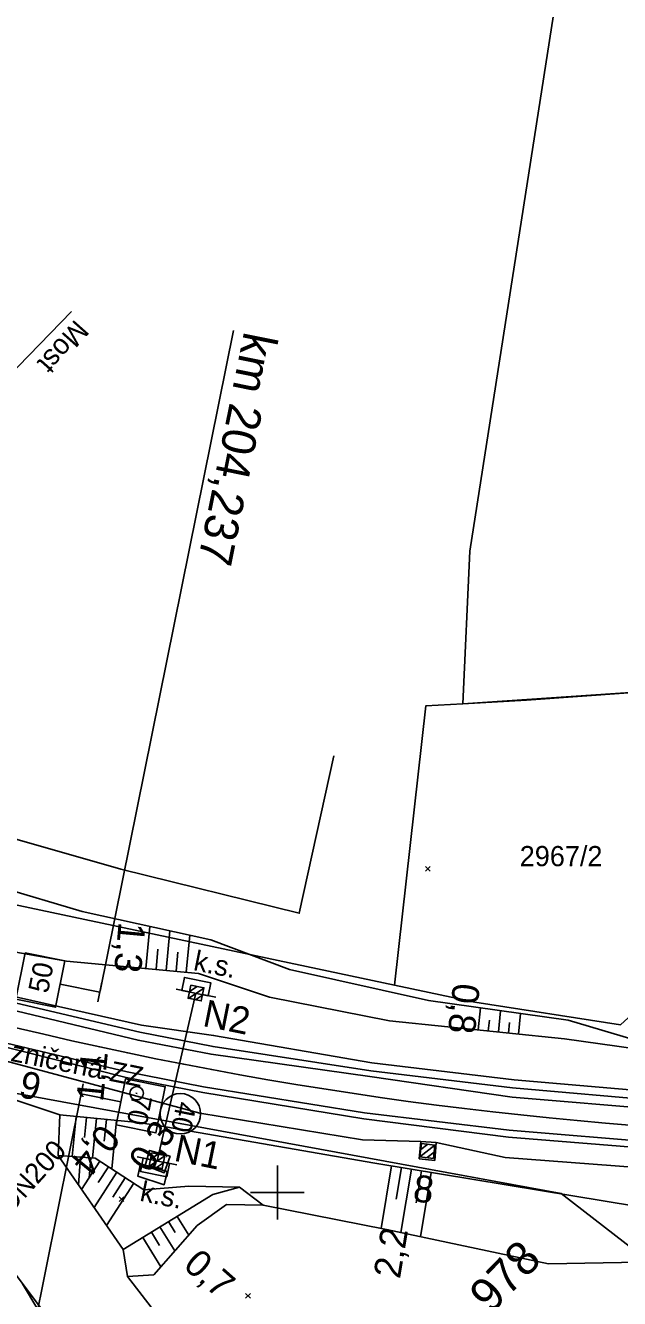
# Model space of a CAD drawing. Extents: x -800194 to -799078, y -1007177 to -1006597.
# Drawn here: x -799718.7 to -799674.6, y -1007007.9 to -1006913.4 of the extents above; entities that cross this region are included whole.
import ezdxf

# ---------------------------------------------------------------- set-up
doc = ezdxf.new("R2010")
doc.units = 0
for name, color, linetype in [('02_Osa_koleje', 7, 'Continuous'), ('Ramove udaje', 7, 'Continuous'), ('Vrstva 11', 7, 'Continuous'), ('Vrstva 12', 7, 'Continuous'), ('Vrstva 17', 7, 'Continuous'), ('Vrstva 18', 7, 'Continuous'), ('Vrstva 2', 7, 'Continuous'), ('Vrstva 23', 7, 'Continuous'), ('Vrstva 25', 7, 'Continuous'), ('Vrstva 4', 7, 'Continuous'), ('Vrstva 43', 7, 'Continuous'), ('Vrstva 48', 7, 'Continuous'), ('Vrstva 49', 7, 'Continuous'), ('Vrstva 5', 7, 'Continuous'), ('Vrstva 50', 7, 'Continuous'), ('Vrstva 53', 7, 'Continuous'), ('Vrstva 55', 7, 'Continuous'), ('Vrstva 57', 7, 'Continuous')]:
    doc.layers.add(name, color=color, linetype=linetype)

msp = doc.modelspace()

# ---------------------------------------------------------------- linework, layer by layer
at = {"layer": '02_Osa_koleje'}
msp.add_arc((-799651.022, -1006703.891), 292, 255.62486, 308.20516, dxfattribs=at)
at = {"layer": 'Ramove udaje'}
for p, q in [((-799700, -1006998), (-799700, -1007002)), ((-799702, -1007000), (-799700, -1007000)), ((-799700, -1007000), (-799698, -1007000))]:
    msp.add_line(p, q, dxfattribs=at)
at = {"layer": 'Vrstva 11'}
for p, q in [((-799706.526, -1006985.106), (-799707.506, -1006984.907)), ((-799706.602, -1006985.6), (-799705.452, -1006984.836)), ((-799706.525, -1006985.099), (-799705.943, -1006984.713)), ((-799706.036, -1006985.204), (-799708.923, -1006997.646)), ((-799706.082, -1006985.705), (-799705.557, -1006985.356)), ((-799705.546, -1006985.304), (-799704.566, -1006985.501)), ((-799689.419, -1006997.352), (-799688.31, -1006996.481)), ((-799689.355, -1006996.825), (-799688.836, -1006996.418)), ((-799709.413, -1006997.548), (-799710.393, -1006997.349)), ((-799709.489, -1006998.042), (-799708.339, -1006997.278)), ((-799709.412, -1006997.541), (-799708.83, -1006997.155)), ((-799688.896, -1006997.418), (-799688.37, -1006997.005)), ((-799708.969, -1006998.147), (-799708.444, -1006997.798)), ((-799708.433, -1006997.746), (-799707.453, -1006997.943))]:
    msp.add_line(p, q, dxfattribs=at)
for points in [[(-799706.427, -1006984.615), (-799705.447, -1006984.813), (-799705.645, -1006985.793), (-799706.625, -1006985.595)], [(-799689.3, -1006996.362), (-799688.307, -1006996.481), (-799688.426, -1006997.474), (-799689.419, -1006997.355)], [(-799709.314, -1006997.057), (-799708.334, -1006997.255), (-799708.532, -1006998.235), (-799709.512, -1006998.037)]]:
    msp.add_lwpolyline(points, close=True, dxfattribs=at)
at = {"layer": 'Vrstva 12'}
for p, q in [((-799709.809, -1006998.009), (-799709.806, -1006998.009)), ((-799708.388, -1006998.534), (-799708.385, -1006998.533))]:
    msp.add_line(p, q, dxfattribs=at)
for points in [[(-799689.347, -1006996.226), (-799688.222, -1006996.296), (-799688.323, -1006997.618), (-799689.475, -1006997.506), (-799689.347, -1006996.226)], [(-799707.958, -1006997.313), (-799708.385, -1006998.533), (-799709.809, -1006998.009), (-799709.473, -1006996.883)], [(-799707.958, -1006997.313), (-799709.473, -1006996.883), (-799709.806, -1006998.009), (-799708.388, -1006998.534), (-799707.958, -1006997.313)]]:
    msp.add_lwpolyline(points, dxfattribs=at)
at = {"layer": 'Vrstva 17'}
for points in [[(-799695.807, -1006967.611), (-799698.37, -1006979.283), (-799711.621, -1006976.014), (-799725.913, -1006971.918), (-799726.806, -1006975.491)], [(-799708.261, -1006998.95), (-799708.384, -1006999.431), (-799710.346, -1006998.801), (-799710.257, -1006998.331)]]:
    msp.add_lwpolyline(points, dxfattribs=at)
at = {"layer": 'Vrstva 18'}
msp.add_line((-799754.68, -1006975.182), (-799715.262, -1006934.616), dxfattribs=at)
at = {"layer": 'Vrstva 23'}
msp.add_lwpolyline([(-799710.163, -1006997.878), (-799708.18, -1006998.442), (-799708.384, -1006999.431), (-799710.346, -1006998.801), (-799710.163, -1006997.878)], dxfattribs=at)
at = {"layer": 'Vrstva 25'}
for points in [[(-799707.094, -1006985.017), (-799706.896, -1006984.037), (-799704.936, -1006984.433), (-799705.134, -1006985.413), (-799707.094, -1006985.017)], [(-799708.002, -1006997.857), (-799708.2, -1006998.837), (-799710.16, -1006998.441), (-799709.962, -1006997.461), (-799708.002, -1006997.857)]]:
    msp.add_lwpolyline(points, dxfattribs=at)
at = {"layer": 'Vrstva 4'}
for points in [[(-799766.319, -1006970.565), (-799760.949, -1006972.542), (-799747.638, -1006977.46), (-799730.549, -1006982.982), (-799710.066, -1006987.578), (-799704.728, -1006988.346), (-799693.001, -1006990.373), (-799682.434, -1006991.64), (-799671.27, -1006992.619), (-799659.31, -1006993.026), (-799648.69, -1006993.125), (-799637.398, -1006992.704), (-799625.913, -1006992.175), (-799614.965, -1006990.831), (-799603.911, -1006989.312), (-799592.728, -1006987.172), (-799581.605, -1006984.547), (-799570.583, -1006981.598), (-799559.909, -1006978.216), (-799542.956, -1006972.25), (-799531.79, -1006967.658), (-799521.285, -1006962.191), (-799511.236, -1006957.129)], [(-799779.678, -1006964.304), (-799766.319, -1006970.565), (-799761.253, -1006973.176), (-799747.77, -1006978.421), (-799730.774, -1006983.8), (-799710.333, -1006988.709), (-799704.916, -1006989.741), (-799693.131, -1006991.407), (-799682.585, -1006992.929), (-799671.325, -1006993.879), (-799659.363, -1006994.45), (-799648.66, -1006994.501), (-799637.23, -1006994.127), (-799626.066, -1006993.335), (-799614.788, -1006992.17), (-799603.669, -1006990.506), (-799592.467, -1006988.452), (-799581.281, -1006985.916), (-799570.22, -1006982.998), (-799559.296, -1006979.606), (-799542.375, -1006973.485), (-799531.236, -1006968.774), (-799520.48, -1006963.762), (-799510.394, -1006958.536)], [(-799776.864, -1006969.085), (-799770.965, -1006971.646), (-799761.91, -1006975.649), (-799748.544, -1006980.777), (-799731.457, -1006986.215), (-799711.132, -1006991.054), (-799705.482, -1006992.16), (-799693.53, -1006994.084), (-799682.801, -1006995.384), (-799671.514, -1006996.319), (-799659.449, -1006996.851), (-799648.588, -1006996.949), (-799637.262, -1006996.573), (-799625.835, -1006995.773), (-799614.546, -1006994.586), (-799603.199, -1006992.945), (-799591.969, -1006990.857), (-799580.647, -1006988.335), (-799569.534, -1006985.311), (-799558.557, -1006981.947), (-799541.405, -1006975.739), (-799530.263, -1006971.071), (-799519.455, -1006966), (-799509.248, -1006960.724)], [(-799776.864, -1006969.085), (-799771.262, -1006971.982), (-799762.131, -1006976.093), (-799748.706, -1006981.286), (-799731.51, -1006986.353), (-799711.222, -1006991.459), (-799705.527, -1006992.587), (-799693.582, -1006994.543), (-799682.85, -1006995.904), (-799671.5, -1006996.805), (-799659.556, -1006997.356), (-799648.616, -1006997.341), (-799637.276, -1006997.071), (-799625.828, -1006996.297), (-799614.43, -1006995.109), (-799603.18, -1006993.475), (-799591.849, -1006991.264), (-799580.564, -1006988.698), (-799569.449, -1006985.746), (-799558.385, -1006982.386), (-799541.268, -1006976.227), (-799530.102, -1006971.505), (-799519.398, -1006966.36), (-799509.087, -1006961.127)], [(-799779.011, -1006963.023), (-799770.632, -1006967.944), (-799766.319, -1006970.565), (-799761.021, -1006972.82), (-799747.748, -1006977.966), (-799730.719, -1006983.271), (-799710.195, -1006988.108), (-799704.765, -1006989.181), (-799693.072, -1006990.965), (-799682.554, -1006992.238), (-799671.266, -1006993.222), (-799659.388, -1006993.765), (-799648.658, -1006993.824), (-799637.385, -1006993.531), (-799625.769, -1006992.728), (-799614.9, -1006991.542), (-799603.91, -1006989.963), (-799592.572, -1006987.892), (-799581.421, -1006985.419), (-799570.327, -1006982.332), (-799559.429, -1006979.066), (-799542.601, -1006973.013), (-799531.454, -1006968.25), (-799520.744, -1006963.214)], [(-799776.864, -1006969.085), (-799771.693, -1006972.522), (-799762.217, -1006976.394), (-799748.898, -1006981.647), (-799733.68, -1006986.66), (-799728.795, -1006987.945), (-799711.349, -1006992.599), (-799705.744, -1006994.116), (-799693.689, -1006996.09), (-799689.347, -1006996.226), (-799688.222, -1006996.296), (-799683.105, -1006997.407), (-799671.667, -1006998.275)]]:
    msp.add_lwpolyline(points, dxfattribs=at)
at = {"layer": 'Vrstva 48'}
for p, q in [((-799709.746, -1006983.382), (-799709.457, -1006980.257)), ((-799708.252, -1006983.521), (-799707.98, -1006980.58)), ((-799706.759, -1006983.659), (-799706.504, -1006980.903)), ((-799708.999, -1006983.452), (-799708.859, -1006981.935)), ((-799707.506, -1006983.59), (-799707.374, -1006982.166)), ((-799685.1, -1006987.935), (-799684.931, -1006986.304)), ((-799683.608, -1006988.09), (-799683.444, -1006986.513)), ((-799682.116, -1006988.245), (-799681.958, -1006986.722)), ((-799684.354, -1006988.013), (-799684.271, -1006987.211)), ((-799682.862, -1006988.168), (-799682.782, -1006987.393)), ((-799714.916, -1006994.364), (-799715.209, -1006997.336)), ((-799714.169, -1006994.437), (-799714.315, -1006995.913)), ((-799713.423, -1006994.511), (-799713.712, -1006997.443)), ((-799712.677, -1006994.585), (-799712.835, -1006996.19)), ((-799711.93, -1006994.658), (-799712.285, -1006998.256)), ((-799714.594, -1006997.38), (-799714.742, -1006999.446)), ((-799713.846, -1006997.433), (-799713.954, -1006998.934)), ((-799713.165, -1006997.685), (-799714.519, -1006999.77)), ((-799712.536, -1006998.093), (-799713.297, -1006999.266)), ((-799691.538, -1006998.023), (-799692.31, -1007002.68)), ((-799690.798, -1006998.146), (-799691.187, -1007000.488)), ((-799690.058, -1006998.269), (-799690.841, -1007002.985)), ((-799689.318, -1006998.392), (-799689.712, -1007000.766)), ((-799711.907, -1006998.502), (-799713.599, -1007001.107)), ((-799710.649, -1006999.319), (-799712.678, -1007002.443)), ((-799711.278, -1006998.911), (-799712.208, -1007000.343)), ((-799688.579, -1006998.514), (-799689.372, -1007003.296)), ((-799708.066, -1007002.169), (-799707.578, -1007002.963)), ((-799707.427, -1007001.776), (-799706.571, -1007003.169)), ((-799709.344, -1007002.954), (-799708.736, -1007003.943)), ((-799708.705, -1007002.561), (-799707.609, -1007004.344)), ((-799709.983, -1007003.347), (-799708.648, -1007005.518))]:
    msp.add_line(p, q, dxfattribs=at)
at = {"layer": 'Vrstva 49'}
for p, q in [((-799689.011, -1006975.814), (-799688.657, -1006976.168)), ((-799689.011, -1006976.168), (-799688.657, -1006975.814)), ((-799716.248, -1006997.261), (-799716.141, -1006994.243)), ((-799711.736, -1007000.327), (-799711.382, -1007000.681)), ((-799711.736, -1007000.681), (-799711.382, -1007000.327)), ((-799702.358, -1007007.501), (-799702.004, -1007007.855)), ((-799702.358, -1007007.855), (-799702.004, -1007007.501))]:
    msp.add_line(p, q, dxfattribs=at)
for points in [[(-799710.319, -1006994.817), (-799708.871, -1006995.032), (-799692.771, -1006997.819), (-799673.296, -1007001.049), (-799659.562, -1007000.479), (-799648.457, -1007000.689), (-799625.451, -1006999.097), (-799615.697, -1006997.513), (-799614.57, -1006997.347), (-799602.963, -1006995.575), (-799579.498, -1006991.091), (-799558.66, -1006984.762), (-799544.861, -1006980.115), (-799538.187, -1006977.215), (-799529.217, -1006973.339), (-799517.856, -1006968.167), (-799516.556, -1006966.997), (-799515.527, -1006966.511), (-799507.817, -1006962.779)], [(-799728.174, -1006980.607), (-799726.806, -1006975.491), (-799714.47, -1006979.159), (-799704.928, -1006981.248), (-799699.097, -1006983.466), (-799688.779, -1006985.763), (-799678.423, -1006987.219), (-799669.363, -1006989.921)], [(-799728.174, -1006980.607), (-799715.637, -1006982.837), (-799705.851, -1006983.743), (-799700.586, -1006985.508), (-799691.67, -1006987.253), (-799678.693, -1006988.601), (-799669.363, -1006989.921)], [(-799733.039, -1007005.939), (-799736.26, -1007003.86), (-799742.34, -1006997.896), (-799743.342, -1006994.901), (-799739.871, -1006991.182), (-799734.968, -1006991.052), (-799728.642, -1006990.92), (-799723.01, -1006991.966), (-799716.141, -1006994.243), (-799710.319, -1006994.817)], [(-799716.248, -1006997.261), (-799711.439, -1007004.242), (-799711.113, -1007006.25), (-799707.442, -1007011.019), (-799702.585, -1007019.595), (-799698.243, -1007027.001), (-799684.872, -1007037.347), (-799668.902, -1007051.666)], [(-799716.248, -1006997.261), (-799713.515, -1006997.457), (-799709.895, -1006999.809), (-799706.577, -1006999.538), (-799702.816, -1006999.606), (-799701.051, -1007000.939), (-799691.907, -1007002.76), (-799679.882, -1007005.3), (-799670.416, -1007005.115), (-799649.119, -1007006.099), (-799641.812, -1007006.94)], [(-799702.816, -1006999.606), (-799704.779, -1007000.148), (-799711.439, -1007004.242)], [(-799711.113, -1007006.25), (-799709.167, -1007006.105), (-799705.943, -1007002.46), (-799703.761, -1007000.905), (-799701.051, -1007000.939)], [(-799718.907, -1007006.786), (-799714.515, -1007014.16), (-799704.214, -1007027.237), (-799692.017, -1007040.081), (-799674.887, -1007054.948)]]:
    msp.add_lwpolyline(points, dxfattribs=at)
at = {"layer": 'Vrstva 5'}
for p, q in [((-799703.26, -1006936.046), (-799713.152, -1006985.058)), ((-799713.166, -1006985.129), (-799716.107, -1006984.535)), ((-799713.314, -1006985.864), (-799713.018, -1006984.394)), ((-799714.395, -1006991.944), (-799714.691, -1006993.414)), ((-799714.543, -1006992.679), (-799711.602, -1006993.273)), ((-799720.48, -1007022.094), (-799714.568, -1006992.803))]:
    msp.add_line(p, q, dxfattribs=at)
for points in [[(-799715.76, -1006982.82), (-799716.453, -1006986.251), (-799719.394, -1006985.657), (-799718.701, -1006982.227)], [(-799711.949, -1006994.988), (-799711.256, -1006991.557), (-799708.315, -1006992.151), (-799709.008, -1006995.581)]]:
    msp.add_lwpolyline(points, close=True, dxfattribs=at)
msp.add_circle((-799707.191, -1006994.163), 1.5, dxfattribs=at)
at = {"layer": 'Vrstva 50'}
msp.add_line((-799710.486, -1006992.629), (-799710.388, -1006992.649), dxfattribs=at)
msp.add_circle((-799710.437, -1006992.639), 0.5, dxfattribs=at)
at = {"layer": 'Vrstva 53'}
msp.add_lwpolyline([(-799679.26, -1006911.01), (-799685.71, -1006952.41), (-799686.25, -1006963.73), (-799670.17, -1006962.64)], dxfattribs=at)
at = {"layer": 'Vrstva 55'}
msp.add_line((-799727.37, -1006976.97), (-799691.32, -1006984.61), dxfattribs=at)
for points in [[(-799686.25, -1006963.73), (-799685.71, -1006952.41), (-799679.26, -1006911.01)], [(-799686.25, -1006963.73), (-799681.51, -1006963.46), (-799670.17, -1006962.64), (-799668.03, -1006961.74)], [(-799691.32, -1006984.61), (-799688.98, -1006963.88), (-799686.25, -1006963.73)], [(-799691.32, -1006984.61), (-799685.35, -1006985.87), (-799674.55, -1006987.57), (-799667.43, -1006981.06)], [(-799667.22, -1007009.16), (-799678.94, -1007000.07), (-799720.83, -1006992.39), (-799728.88, -1006993.59), (-799733.28, -1006992.13)], [(-799733.28, -1006992.13), (-799723.72, -1007000.38), (-799700.54, -1007031.23)]]:
    msp.add_lwpolyline(points, dxfattribs=at)

# ---------------------------------------------------------------- texts
at = {"layer": 'Vrstva 11'}
for s, rotation, p in [('N2', 348.58947, (-799705.617, -1006987.633)), ('9', 346.46066, (-799719.279, -1006992.868)), ('N1', 348.58947, (-799707.745, -1006997.634)), ('8', 353.12702, (-799690.001, -1007000.65))]:
    msp.add_text(s, height=2, rotation=rotation, dxfattribs=at).set_placement(p)
at = {"layer": 'Vrstva 18'}
msp.add_text('Most', height=1.5, rotation=228.32626, dxfattribs=at).set_placement((-799714.987, -1006935.156))
at = {"layer": 'Vrstva 2'}
msp.add_text('evid. km 101,978', height=2.5, rotation=45.83096, dxfattribs=at).set_placement((-799698.03, -1007023.349))
at = {"layer": 'Vrstva 25'}
for p in [(-799706.29, -1006983.492), (-799710.262, -1007000.61)]:
    msp.add_text('k.s.', height=1.5, rotation=348.58947, dxfattribs=at).set_placement(p)
at = {"layer": 'Vrstva 43'}
msp.add_text('DN200', height=1.5, rotation=47.69501, dxfattribs=at).set_placement((-799719.754, -1007001.594))
at = {"layer": 'Vrstva 48'}
for s, rotation, p in [('1,3', 264.71056, (-799711.765, -1006979.895)), ('0,8', 264.06961, (-799686.958, -1006984.411)), ('1,1', 84.36932, (-799712.931, -1006993.316)), ('0,4', 230.6701, (-799713.067, -1006994.798)), ('0,3', 56.98726, (-799709.468, -1006998.657)), ('2,2', 80.58301, (-799690.907, -1007006.463)), ('0,7', 318.50726, (-799707.069, -1007005.538))]:
    msp.add_text(s, height=2, rotation=rotation, dxfattribs=at).set_placement(p)
at = {"layer": 'Vrstva 5'}
for s, height, rotation, p in [('km 204,237', 2.5, 258.58947, (-799702.455, -1006936.038)), ('50', 1.5, 78.58947, (-799717.023, -1006985.282)), ('70', 1.5, 258.58947, (-799710.735, -1006992.65)), ('40', 1.5, 258.58947, (-799707.452, -1006993.178))]:
    msp.add_text(s, height=height, rotation=rotation, dxfattribs=at).set_placement(p)
at = {"layer": 'Vrstva 50'}
msp.add_text('zničená ZZ', height=1.5, rotation=348.58947, dxfattribs=at).set_placement((-799719.846, -1006990.228))
at = {"layer": 'Vrstva 57'}
msp.add_text('2967/2', height=1.5, dxfattribs=at).set_placement((-799682.02, -1006975.79))

doc.saveas('drawing.dxf')
